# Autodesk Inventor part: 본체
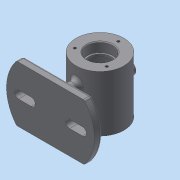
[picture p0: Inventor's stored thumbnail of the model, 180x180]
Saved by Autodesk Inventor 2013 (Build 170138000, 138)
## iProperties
Created: 2017-12
Part Number: 본체
Material: 일반
Document SubType Name: Modeling
Designer: dgall
Density: 1 g/cm^3
Author: dgall
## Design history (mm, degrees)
sketch "스케치1"
  geometry: C1 r 30 at (0, 0); 1 further point
  constraints: 1 centre point, 1 coincident
  dimensions: "d0" = 60 diameter of C1
extrude "돌출1" new body sketch "스케치1" stored distance "d2" = 70; taper "d3" = 0 deg
node "작업 평면1"
sketch "스케치2"
  geometry: L1 (42.426, 35)-(-42.426, 35); L2 (42.426, -35)-(-42.426, -35); A1 r 55 centre (0, 0) between (42.426, -35) and (42.426, 35); A2 r 55 centre (0, 0) between (-42.426, 35) and (-42.426, -35); 2 further points
  constraints: 4 end point, 4 point on circle, 2 centre point, 2 parallel, 1 coincident, 1 horizontal, 1 midpoint, 1 vertical alignment
  dimensions: "d7" = 70 distance between parallel lines of L2 L1; "d9" = 55 radius of A2
extrude "돌출2" join sketch "스케치2" distance "d10" = 10; taper "d11" = 0 deg
fillet "모깎기1" dims "d12" = 3
fillet "모깎기2" dims "d13" = 3
sketch "스케치3"
  geometry: L1 (-40, -5)-(-24, -5); L2 (-40, 5)-(-24, 5); L3 (40, -5)-(24, -5); L4 (24, 5)-(40, 5); A1 r 52 centre (0, 0) between (40.988, -32) and (40.988, 32) reference; A2 r 5 centre (-40, 0) between (-40, 5) and (-40, -5); A3 r 5 centre (-24, 0) between (-24, -5) and (-24, 5); A4 r 5 centre (24, 0) between (24, 5) and (24, -5); A5 r 5 centre (40, 0) between (40, -5) and (40, 5)
  constraints: 8 end point, 8 point on circle, 6 tangent, 4 centre point, 4 horizontal alignment, 2 parallel, 1 equal radius, 1 horizontal
  dimensions: "d14" = 16 distance of A2.centre A3.centre; "d16" = 24 distance of A3.centre A1.centre; "d17" = 16 distance of A5.centre A4.centre; "d18" = 24 distance of A1.centre A4.centre; "d19" = 5 radius of A2; "d20" = 5 radius of A4
extrude "돌출3" cut sketch "스케치3" distance "d21" = 10; taper "d22" = 0 deg
sketch "스케치4"
  geometry: L1 (-40.988, 32)-(40.988, 32) reference; L2 (5, 15)-(5, -15); L3 (-5, 15)-(-5, -15); A1 r 52 centre (0, 0) between (40.988, -32) and (40.988, 32) reference; A2 r 5 centre (0, 15) between (5, 15) and (-5, 15); A3 r 5 centre (0, -15) between (-5, -15) and (5, -15); 1 further point
  constraints: 4 end point, 4 point on circle, 2 centre point, 2 tangent, 2 vertical alignment, 1 equal radius, 1 horizontal alignment, 1 midpoint, 1 perpendicular
  dimensions: "d23" = 5 radius of A2; "d25" = 30 distance of A3.centre A2.centre; "d26" = 15 distance of A2.centre A1.centre
extrude "돌출4" join sketch "스케치4" stored distance "d27" = 10; taper "d28" = 0 deg
fillet "모깎기3" dims "d29" = 5
node "작업 평면2"
sketch "스케치5"
  geometry: C1 r 8 at (0, 0); 1 further point
  constraints: 1 centre point, 1 coincident
  dimensions: "d31" = 16 diameter of C1
extrude "돌출5" join sketch "스케치5" stored distance "d33" = 10; taper "d34" = 0 deg
sketch "스케치6"
  geometry: L1 (-30, -35)-(30, -35) reference; L2 (30, 35)-(-30, 35) reference; L3 (0, -35)-(0, 35); L4 (0, -35)-(16, -35); L5 (16, -35)-(16, -23); L6 (16, -23)-(14, -23); L7 (14, -23)-(14, -20); L8 (14, -20)-(22, -20); L9 (25, -17)-(25, 17); L10 (22, 20)-(14, 20); L11 (14, 20)-(14, 23); L12 (14, 23)-(16, 23); L13 (16, 23)-(16, 35); L14 (16, 35)-(0, 35); A1 r 3 centre (22, 17) between (25, 17) and (22, 20); A2 r 3 centre (22, -17) between (22, -20) and (25, -17); 1 further point
  constraints: 24 end point, 5 parallel, 4 point on circle, 4 tangent, 3 collinear, 3 perpendicular, 2 centre point, 2 midpoint, 2 point on line, 1 equal radius, 1 horizontal
  dimensions: "d35" = 28 diameter of L7 L3; "d37" = 32 diameter of L5 L3; "d38" = 32 diameter of L13 L3; "d39" = 28 diameter of L11 L3; "d40" = 50 diameter of L9 L3; "d41" = 40 distance between parallel lines of L10 L8; "d42" = 12 distance of L4.end L5.end; "d43" = 3 radius of A1
revolve "회전1" sketch "스케치6" stored, may be unused: angle "d44" = 90 deg
fillet "모깎기4" dims "d45" = 0.3
chamfer "모따기1" distance "d46" = 1; stored, may be unused: second distance "d47" = 2, angle "d48" = 45 deg
chamfer "모따기2" distance "d49" = 1; stored, may be unused: second distance "d50" = 2, angle "d51" = 45 deg
hole "구멍1" diameter "d54" = 8; stored, may be unused: countersink angle "d58" = 90 deg, drill point angle "d60" = 0 deg; dims "d52" = 10, "d53" = 10, "d55" = 6, "d56" = 4, "d57" = 2, "d59" = 8
chamfer "모따기3" distance "d61" = 1; stored, may be unused: second distance "d62" = 2, angle "d63" = 45 deg
sketch "스케치7" dims "d64" = 46
  geometry: C1 r 30 at (0, 0) reference; C2 r 17 at (0, 0) reference; 2 further points
  constraints: 2 vertical alignment, 1 coincident, 2 other
hole "구멍2" sketch "스케치7" at (0, 23) diameter "d66" = 3.242; stored, may be unused: countersink angle "d70" = 90 deg, drill point angle "d72" = 118 deg; dims "d67" = 8, "d68" = 4, "d69" = 2, "d71" = 10
fillet "모깎기5" dims "d76" = 3
node "작업 평면3"
sketch "스케치8"
  geometry: L1 (-30, -35)-(-30, 35) reference; L2 (-30, -35)-(30, -35) reference; 2 further points
  constraints: 1 other
  dimensions: "d78" = 30 distance from line of L1 point (0, 0); "d79" = 35 distance from line of point (0, 0) L2
feature "엠보싱1" sketch "스케치8" dims "d80" = 0.5, "d81" = 0
node "솔리드1"
pattern_circular "원형 패턴1" dims angle "d74" = 360 deg
mirror "대칭1"
other parameters: "d4" = -62, "d30" = 37
